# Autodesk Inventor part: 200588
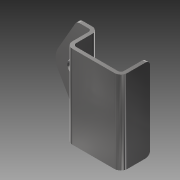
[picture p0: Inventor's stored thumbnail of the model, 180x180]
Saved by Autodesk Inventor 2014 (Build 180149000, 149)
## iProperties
Created: 2007-10
Part Number: 200588
Document SubType Name: Modeling
Designer: TH
Density: 7.85 g/cm^3
Mass: 178.858 g
Surface Area: 163.354 cm^2
Volume: 22.7845 cm^3
Material: Steel
Description: BALL SCREW BRACKET
Appearance: Steel - Polished
Component Category: Lower Component
Author: TH
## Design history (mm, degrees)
sketch "Sketch1"
  geometry: L1 (-70.088, 0)-(40.427, 0) reference; L2 (0, 6.595)-(0, -31.595) reference; L3 (20.5, 0)-(20.5, -19.5); L4 (18, -22)-(-18, -22); L5 (-20.5, -19.5)-(-20.5, -5.5); L6 (-26, 0)-(-54.3, 0); L7 (-54.3, 0)-(-54.3, -3); L8 (-54.3, -3)-(-26, -3); L9 (-23.5, -5.5)-(-23.5, -19.5); L10 (-18, -25)-(18, -25); L11 (23.5, -19.5)-(23.5, 0); L12 (23.5, 0)-(20.5, 0); A1 r 2.5 centre (-26, -5.5) between (-23.5, -5.5) and (-26, -3); A2 r 2.5 centre (-18, -19.5) between (-20.5, -19.5) and (-18, -22); A3 r 2.5 centre (18, -19.5) between (18, -22) and (20.5, -19.5); A4 r 5.5 centre (-26, -5.5) between (-20.5, -5.5) and (-26, 0); A5 r 5.5 centre (-18, -19.5) between (-23.5, -19.5) and (-18, -25); A6 r 5.5 centre (18, -19.5) between (18, -25) and (23.5, -19.5); 2 further points
  constraints: 20 end point, 12 point on circle, 12 tangent, 6 centre point, 6 point on line, 4 equal radius, 4 parallel, 4 perpendicular, 1 collinear
  dimensions: "d0" = 3 distance between parallel lines of L11 L3; "d1" = 3 distance between parallel lines of L8 L1 (= d0); "d2" = 3 distance between parallel lines of L5 L9 (= d0); "d3" = 3 distance between parallel lines of L10 L4 (= d0); "d4" = 41 distance between parallel lines of L5 L3; "d5" = 20.5 distance between parallel lines of L2 L5 (= 0.5 x d4); "d6" = 22 distance between parallel lines of L1 L4; "d7" = 33.8 distance between parallel lines of L7 L5; "d8" = 2.5 radius of A1; "d9" = 5.5 radius of A4
extrude "Extrusion1" new body sketch "Sketch1" stored distance "d10" = 71; taper "d11" = 0 deg
sketch "Sketch2"
  geometry: L1 (0, 0)-(28.3, 0) reference; L2 (28.3, 71)-(0, 71) reference; L3 (0, 0)-(0, 71) reference; L4 (54.3, 35.5)-(0, 35.5); L5 (2.144, 27.5)-(18.021, 0); L6 (2.144, 43.5)-(18.021, 71); L7 (33.8, 71)-(33.8, 0) reference; A1 r 16 centre (16, 35.5) between (2.144, 43.5) and (2.144, 27.5)
  constraints: 6 end point, 3 point on circle, 3 point on line, 2 tangent, 1 centre point, 1 midpoint
  dimensions: "d13" = 30 deg angle of L3 L5; "d14" = 30 deg angle of L3 L6 (= d13); "d15" = 16 radius of A1
extrude "Extrusion2" cut sketch "Sketch2" stored distance "d17" = 71; taper "d18" = 0 deg
fillet "Fillet1" dims "d19" = 4
sketch "Sketch3"
  geometry: C1 r 6 at (-12.3, 35.5); A1 r 16 centre (-12.3, 35.5) between (-26.156, 43.5) and (-26.156, 27.5) reference; 1 further point
  constraints: 1 centre point, 1 coincident
  dimensions: "d20" = 12 diameter of C1
extrude "Extrusion3" cut sketch "Sketch3" stored distance "d21" = 71; taper "d22" = 0 deg
body "Solid1"
other parameters: "d12" = 32
